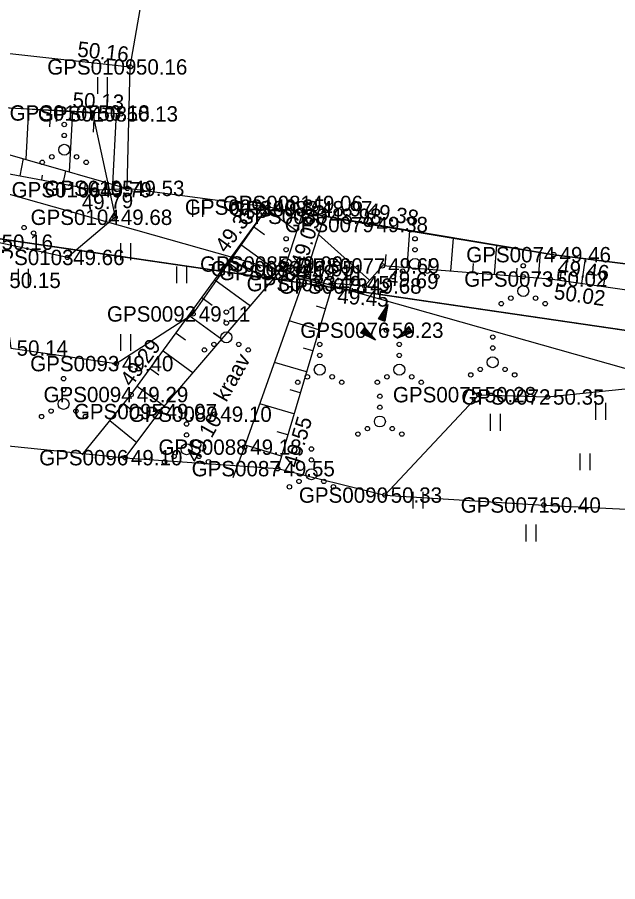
# Model space of a CAD drawing. Extents: x 551623 to 559850, y 6561220 to 6567135.
# Drawn here: x 556014.76 to 556042.11, y 6565327.62 to 6565367.01 of the extents above; entities that cross this region are included whole.
import ezdxf

# ---------------------------------------------------------------- set-up
doc = ezdxf.new("R2010")
doc.units = 0
for name, color, linetype in [('HALJASTUS', 7, 'Continuous'), ('KORGUS-EH2000', 7, 'Continuous'), ('KPOHULIIN', 7, 'Continuous'), ('MOOTKORG-EH2000', 7, 'Continuous'), ('MOOTMPUNKT', 7, 'Continuous'), ('MOOTNR', 7, 'Continuous'), ('MOOTPIIR', 7, 'Continuous'), ('PIIR', 7, 'Continuous'), ('RELJEEF', 7, 'Continuous'), ('TEE', 7, 'Continuous'), ('VEEKOGU', 7, 'Continuous')]:
    doc.layers.add(name, color=color, linetype=linetype)

msp = doc.modelspace()

# ---------------------------------------------------------------- linework, layer by layer
at = {"layer": 'HALJASTUS'}
for p, q in [((556018.404, 6565364.285), (556018.404, 6565363.524)), ((556018.859, 6565364.285), (556018.859, 6565363.524)), ((556022.737, 6565358.682), (556022.737, 6565357.921)), ((556023.192, 6565358.682), (556023.192, 6565357.921)), ((556019.463, 6565356.707), (556019.463, 6565355.946)), ((556019.918, 6565356.707), (556019.918, 6565355.946)), ((556014.792, 6565355.55), (556014.792, 6565354.789)), ((556015.247, 6565355.55), (556015.247, 6565354.789)), ((556022.015, 6565355.647), (556022.015, 6565354.886)), ((556022.47, 6565355.647), (556022.47, 6565354.886)), ((556019.463, 6565352.563), (556019.463, 6565351.802)), ((556019.918, 6565352.563), (556019.918, 6565351.802)), ((556041.092, 6565349.431), (556041.092, 6565348.67)), ((556041.548, 6565349.431), (556041.548, 6565348.67)), ((556036.301, 6565348.931), (556036.301, 6565348.17)), ((556036.756, 6565348.931), (556036.756, 6565348.17)), ((556040.382, 6565347.124), (556040.382, 6565346.363)), ((556040.837, 6565347.124), (556040.837, 6565346.363)), ((556032.777, 6565345.384), (556032.777, 6565344.623)), ((556033.232, 6565345.384), (556033.232, 6565344.623)), ((556037.924, 6565343.888), (556037.924, 6565343.127)), ((556038.38, 6565343.888), (556038.38, 6565343.127))]:
    msp.add_line(p, q, dxfattribs=at)
for points in [[(555993.466, 6565364.067), (556009.179, 6565363.204), (556018.189, 6565362.647), (556019.213, 6565357.893), (556017.04, 6565356.065), (556013.782, 6565356.759), (556014.467, 6565351.934), (556019.265, 6565351.225), (556022.764, 6565353.488), (556026.171, 6565358.357)], [(556031.505, 6565345.235), (556035.788, 6565349.81), (556038.903, 6565349.705), (556046.564, 6565350.502), (556056.627, 6565352.652), (556057.538, 6565354.856)]]:
    msp.add_lwpolyline(points, dxfattribs=at)
for centre, radius in [((556016.896, 6565362.122), 0.1), ((556016.896, 6565361.622), 0.1), ((556016.896, 6565360.972), 0.25), ((556016.331, 6565360.647), 0.1), ((556017.461, 6565360.647), 0.1), ((556015.896, 6565360.397), 0.1), ((556017.896, 6565360.397), 0.1), ((556015.066, 6565357.424), 0.1), ((556015.501, 6565357.174), 0.1), ((556027.003, 6565356.913), 0.1), ((556032.874, 6565356.913), 0.1), ((556027.003, 6565356.413), 0.1), ((556032.874, 6565356.413), 0.1), ((556027.003, 6565355.763), 0.25), ((556032.874, 6565355.763), 0.25), ((556026.438, 6565355.438), 0.1), ((556027.568, 6565355.438), 0.1), ((556032.309, 6565355.438), 0.1), ((556033.439, 6565355.438), 0.1), ((556037.804, 6565355.683), 0.1), ((556026.003, 6565355.188), 0.1), ((556028.003, 6565355.188), 0.1), ((556031.874, 6565355.188), 0.1), ((556033.874, 6565355.188), 0.1), ((556037.804, 6565355.183), 0.1), ((556037.804, 6565354.533), 0.25), ((556037.239, 6565354.208), 0.1), ((556038.369, 6565354.208), 0.1), ((556036.804, 6565353.958), 0.1), ((556038.804, 6565353.958), 0.1), ((556024.279, 6565353.575), 0.1), ((556024.279, 6565353.075), 0.1), ((556024.279, 6565352.425), 0.25), ((556036.413, 6565352.437), 0.1), ((556023.279, 6565351.85), 0.1), ((556023.714, 6565352.1), 0.1), ((556024.844, 6565352.1), 0.1), ((556025.279, 6565351.85), 0.1), ((556028.535, 6565352.099), 0.1), ((556032.158, 6565352.099), 0.1), ((556036.413, 6565351.937), 0.1), ((556028.535, 6565351.599), 0.1), ((556032.158, 6565351.599), 0.1), ((556028.535, 6565350.949), 0.25), ((556032.158, 6565350.949), 0.25), ((556036.413, 6565351.287), 0.25), ((556035.413, 6565350.712), 0.1), ((556035.848, 6565350.962), 0.1), ((556036.978, 6565350.962), 0.1), ((556037.413, 6565350.712), 0.1), ((556016.864, 6565350.539), 0.1), ((556027.535, 6565350.374), 0.1), ((556027.97, 6565350.624), 0.1), ((556029.1, 6565350.624), 0.1), ((556029.535, 6565350.374), 0.1), ((556031.158, 6565350.374), 0.1), ((556031.593, 6565350.624), 0.1), ((556032.723, 6565350.624), 0.1), ((556033.158, 6565350.374), 0.1), ((556016.864, 6565350.039), 0.1), ((556016.864, 6565349.389), 0.25), ((556031.273, 6565349.738), 0.1), ((556031.273, 6565349.238), 0.1), ((556015.864, 6565348.814), 0.1), ((556016.299, 6565349.064), 0.1), ((556017.429, 6565349.064), 0.1), ((556017.864, 6565348.814), 0.1), ((556031.273, 6565348.588), 0.25), ((556022.467, 6565348.474), 0.1), ((556022.467, 6565347.974), 0.1), ((556030.273, 6565348.013), 0.1), ((556030.708, 6565348.263), 0.1), ((556031.838, 6565348.263), 0.1), ((556032.273, 6565348.013), 0.1), ((556022.467, 6565347.324), 0.25), ((556028.155, 6565347.335), 0.1), ((556021.467, 6565346.749), 0.1), ((556021.902, 6565346.999), 0.1), ((556023.032, 6565346.999), 0.1), ((556023.467, 6565346.749), 0.1), ((556028.155, 6565346.835), 0.1), ((556028.155, 6565346.185), 0.25), ((556027.155, 6565345.61), 0.1), ((556027.59, 6565345.86), 0.1), ((556028.72, 6565345.86), 0.1), ((556029.155, 6565345.61), 0.1)]:
    msp.add_circle(centre, radius, dxfattribs=at)
at = {"layer": 'KORGUS-EH2000'}
for centre in [(556019.902, 6565364.745), (556019.475, 6565362.606), (556018.278, 6565359.149), (556026.171, 6565358.357), (556030.86, 6565357.563), (556039.198, 6565356.19), (556017.04, 6565356.065), (556027.486, 6565355.551), (556031.391, 6565355.68), (556039.035, 6565355.08), (556029.124, 6565354.87), (556022.764, 6565353.488), (556031.569, 6565352.746), (556019.943, 6565349.815), (556035.788, 6565349.81), (556038.903, 6565349.705), (556023.747, 6565348.921), (556026.62, 6565346.439), (556031.505, 6565345.235), (556038.736, 6565344.782)]:
    msp.add_circle(centre, 0.1, dxfattribs=at)
at = {"layer": 'KPOHULIIN'}
msp.add_lwpolyline([(555766.29, 6565358.132), (555774.476, 6565357.809), (555774.476, 6565357.809), (555822.758, 6565358.143), (555870.36, 6565358.416), (555918.911, 6565358.624), (555918.911, 6565358.624), (555966.511, 6565359.063), (556012.012, 6565359.614), (556063.102, 6565345.172), (556063.102, 6565345.172), (556112.628, 6565331.115), (556160.567, 6565309.951), (556211.02, 6565287.529)], dxfattribs=at)
at = {"layer": 'MOOTMPUNKT'}
for centre in [(556019.902, 6565364.745), (556018.189, 6565362.647), (556019.475, 6565362.606), (556018.278, 6565359.149), (556019.769, 6565359.212), (556026.171, 6565358.357), (556027.899, 6565358.524), (556028.333, 6565358.284), (556019.213, 6565357.893), (556028.747, 6565357.937), (556030.86, 6565357.563), (556039.198, 6565356.19), (556017.04, 6565356.065), (556027.003, 6565355.763), (556027.486, 6565355.551), (556031.391, 6565355.68), (556027.931, 6565355.378), (556039.035, 6565355.08), (556029.124, 6565354.87), (556030.571, 6565354.761), (556022.764, 6565353.488), (556031.569, 6565352.746), (556019.265, 6565351.225), (556019.943, 6565349.815), (556035.788, 6565349.81), (556038.903, 6565349.705), (556021.253, 6565349.04), (556023.747, 6565348.921), (556025.108, 6565347.419), (556019.674, 6565346.939), (556026.62, 6565346.439), (556031.505, 6565345.235), (556038.736, 6565344.782)]:
    msp.add_circle(centre, 0.1, dxfattribs=at)
at = {"layer": 'MOOTPIIR'}
for points in [[(556057.929, 6565353.821), (556039.198, 6565356.19), (556028.747, 6565357.937), (556026.171, 6565358.357), (556019.769, 6565359.212), (556019.902, 6565364.745), (556021.558, 6565374.265), (556015.152, 6565374.331), (556012.73, 6565375.394), (555993.907, 6565375.821), (555986.511, 6565374.867), (555981.259, 6565364.203), (555966.865, 6565362.926), (555942.733, 6565362.646), (555918.997, 6565362.459), (555899.983, 6565361.794), (555880.558, 6565361.528), (555870.644, 6565361.764), (555852.219, 6565361.421)], [(555839.435, 6565355.215), (555871.496, 6565354.829), (555900.084, 6565356.085), (555918.855, 6565355.549), (555942.97, 6565356.268), (555966.756, 6565353.298), (555985.371, 6565350.605), (555996.731, 6565349.216), (556009.016, 6565348.025), (556019.674, 6565346.939), (556026.62, 6565346.439), (556031.505, 6565345.235), (556038.736, 6565344.782), (556063.163, 6565343.594)]]:
    msp.add_lwpolyline(points, dxfattribs=at)
at = {"layer": 'PIIR'}
for points in [[(555860.69, 6565787.05), (556134.83, 6565867.67), (556136.76, 6565868.24), (556138.68, 6565868.81), (556304.72, 6565917.64), (556407.28, 6565947.65), (556409.2, 6565948.21), (556411.12, 6565948.77), (556555.39, 6565990.98), (556602.55, 6565855.41), (556340.11, 6565662.55), (556145.23, 6565518.55), (556122.95, 6565328.71), (556065.95, 6565349.3), (555986.85, 6565360.88), (555889.86, 6565359.34), (555877.35, 6565546.73)], [(555766.77, 6565362.31), (555785.15, 6565359.9), (555792.17, 6565359.86), (555889.86, 6565359.34), (555986.85, 6565360.88), (556065.95, 6565349.3), (556122.95, 6565328.71), (556199.38, 6565295.85), (556198.85, 6565282.81), (556195.83, 6565275.41), (556189.32, 6565262.35), (556176.88, 6565235.57), (556133.25, 6565139.15), (556097.67, 6565060.64), (555982.17, 6564796.57), (555965.54, 6564731.83), (555935.2, 6564801.96), (555871.92, 6565015.39), (555870.22, 6565021.13), (555867.36, 6565030.76)]]:
    msp.add_lwpolyline(points, close=True, dxfattribs=at)
at = {"layer": 'RELJEEF'}
for p, q in [((556015.267, 6565362.821), (556015.15, 6565360.535)), ((556016.266, 6565362.77), (556016.227, 6565362.015)), ((556017.265, 6565362.719), (556017.124, 6565359.97)), ((556018.263, 6565362.668), (556018.218, 6565361.774)), ((556019.262, 6565362.617), (556019.098, 6565359.404)), ((556014.887, 6565359.781), (556015.034, 6565360.568)), ((556016.853, 6565359.415), (556016.965, 6565360.015)), ((556015.87, 6565359.598), (556015.909, 6565359.806)), ((556018.828, 6565359.172), (556018.815, 6565359.485)), ((556017.836, 6565359.232), (556017.865, 6565359.384)), ((556026.112, 6565358.276), (556027.492, 6565357.27)), ((556025.523, 6565357.468), (556026.016, 6565357.108)), ((556030.807, 6565355.025), (556028.481, 6565357.102)), ((556032.51, 6565355.592), (556032.642, 6565357.27)), ((556034.504, 6565355.436), (556034.622, 6565356.944)), ((556024.933, 6565356.66), (556026.681, 6565355.386)), ((556036.498, 6565355.279), (556036.603, 6565356.618)), ((556038.492, 6565355.123), (556038.583, 6565356.292)), ((556031.513, 6565355.67), (556031.555, 6565356.199)), ((556033.507, 6565355.514), (556033.545, 6565355.992)), ((556040.475, 6565354.873), (556040.639, 6565356.008)), ((556024.344, 6565355.852), (556024.85, 6565355.483)), ((556029.927, 6565354.81), (556029.992, 6565355.674)), ((556035.501, 6565355.357), (556035.534, 6565355.784)), ((556037.495, 6565355.201), (556037.524, 6565355.577)), ((556039.485, 6565355.015), (556039.534, 6565355.351)), ((556023.755, 6565355.044), (556025.377, 6565353.861)), ((556029.069, 6565354.683), (556027.817, 6565355.055)), ((556041.465, 6565354.73), (556041.515, 6565355.076)), ((556023.166, 6565354.236), (556023.634, 6565353.895)), ((556031.214, 6565353.272), (556031.634, 6565353.912)), ((556031.634, 6565353.912), (556031.494, 6565353.157)), ((556028.784, 6565353.725), (556028.393, 6565353.841)), ((556031.314, 6565353.422), (556031.564, 6565353.527)), ((556031.364, 6565353.497), (556031.489, 6565353.552)), ((556031.414, 6565353.572), (556031.584, 6565353.647)), ((556031.464, 6565353.647), (556031.594, 6565353.707)), ((556031.489, 6565353.552), (556031.574, 6565353.587)), ((556031.509, 6565353.722), (556031.609, 6565353.762)), ((556031.559, 6565353.797), (556031.619, 6565353.822)), ((556031.609, 6565353.872), (556031.629, 6565353.882)), ((556022.577, 6565353.428), (556024.073, 6565352.337)), ((556028.499, 6565352.766), (556027.147, 6565353.168)), ((556031.214, 6565353.272), (556031.539, 6565353.412)), ((556031.214, 6565353.272), (556031.494, 6565353.157)), ((556031.214, 6565353.272), (556031.214, 6565353.272)), ((556031.264, 6565353.347), (556031.549, 6565353.467)), ((556031.279, 6565353.247), (556031.529, 6565353.352)), ((556031.344, 6565353.217), (556031.519, 6565353.292)), ((556031.414, 6565353.192), (556031.509, 6565353.232)), ((556031.479, 6565353.167), (556031.494, 6565353.172)), ((556030.573, 6565352.871), (556030.388, 6565352.631)), ((556030.488, 6565352.761), (556030.513, 6565352.576)), ((556030.528, 6565352.816), (556030.563, 6565352.546)), ((556030.573, 6565352.871), (556031.078, 6565352.301)), ((556030.573, 6565352.871), (556030.618, 6565352.521)), ((556030.573, 6565352.871), (556030.573, 6565352.871)), ((556030.633, 6565352.806), (556030.673, 6565352.496)), ((556030.693, 6565352.736), (556030.728, 6565352.471)), ((556032.052, 6565352.366), (556032.592, 6565352.911)), ((556032.762, 6565352.661), (556032.412, 6565352.726)), ((556032.722, 6565352.716), (556032.457, 6565352.771)), ((556032.682, 6565352.776), (556032.497, 6565352.811)), ((556032.642, 6565352.836), (556032.542, 6565352.856)), ((556032.602, 6565352.896), (556032.582, 6565352.896)), ((556032.762, 6565352.661), (556032.592, 6565352.911)), ((556021.988, 6565352.62), (556022.418, 6565352.306)), ((556031.078, 6565352.301), (556030.388, 6565352.631)), ((556030.398, 6565352.646), (556030.403, 6565352.626)), ((556030.443, 6565352.701), (556030.458, 6565352.601)), ((556030.753, 6565352.671), (556030.768, 6565352.531)), ((556030.768, 6565352.531), (556030.783, 6565352.441)), ((556030.808, 6565352.601), (556030.838, 6565352.416)), ((556030.868, 6565352.536), (556030.888, 6565352.391)), ((556030.928, 6565352.466), (556030.943, 6565352.366)), ((556030.988, 6565352.401), (556030.998, 6565352.336)), ((556031.048, 6565352.331), (556031.053, 6565352.311)), ((556032.762, 6565352.661), (556032.052, 6565352.366)), ((556032.092, 6565352.381), (556032.077, 6565352.386)), ((556032.177, 6565352.416), (556032.117, 6565352.431)), ((556032.262, 6565352.451), (556032.157, 6565352.471)), ((556032.342, 6565352.486), (556032.202, 6565352.516)), ((556032.427, 6565352.521), (556032.242, 6565352.556)), ((556032.377, 6565352.581), (556032.287, 6565352.601)), ((556032.592, 6565352.591), (556032.327, 6565352.641)), ((556032.677, 6565352.626), (556032.372, 6565352.686)), ((556032.512, 6565352.556), (556032.377, 6565352.581)), ((556032.762, 6565352.661), (556032.762, 6565352.661)), ((556021.398, 6565351.812), (556022.769, 6565350.812)), ((556028.214, 6565351.807), (556027.794, 6565351.932)), ((556027.93, 6565350.849), (556026.477, 6565351.28)), ((556020.809, 6565351.004), (556021.202, 6565350.718)), ((556020.22, 6565350.196), (556021.465, 6565349.288)), ((556027.645, 6565349.89), (556027.194, 6565350.024)), ((556019.609, 6565349.405), (556019.966, 6565349.115)), ((556027.36, 6565348.932), (556025.808, 6565349.393)), ((556018.979, 6565348.628), (556020.199, 6565347.637)), ((556027.076, 6565347.973), (556026.595, 6565348.116)), ((556026.791, 6565347.014), (556025.138, 6565347.505))]:
    msp.add_line(p, q, dxfattribs=at)
for points in [[(555993.3, 6565364.022), (556010.432, 6565361.886), (556019.769, 6565359.212)], [(556019.475, 6565362.606), (556010.471, 6565363.067), (555993.3, 6565364.022), (556010.587, 6565360.582), (556018.278, 6565359.149), (556019.769, 6565359.212)], [(556017.718, 6565347.076), (556019.943, 6565349.815), (556026.171, 6565358.357)], [(556028.747, 6565357.937), (556030.86, 6565357.563), (556039.198, 6565356.19), (556057.929, 6565353.821), (556064.592, 6565351.829), (556088.936, 6565343.79), (556116.503, 6565332.956), (556130.776, 6565326.047), (556146.22, 6565319.093), (556161.9, 6565312.316), (556182.877, 6565303.186), (556190.092, 6565300.488), (556198.955, 6565296.142)], [(556198.951, 6565295.377), (556198.427, 6565295.218), (556190.116, 6565299.053), (556182.032, 6565302.053), (556161.506, 6565310.813), (556145.447, 6565317.76), (556130.182, 6565324.921), (556115.272, 6565331.25), (556088.426, 6565342.556), (556064.014, 6565350.434), (556058.394, 6565352.289), (556039.035, 6565355.08), (556031.391, 6565355.68), (556030.571, 6565354.761), (556029.124, 6565354.87), (556026.62, 6565346.439)]]:
    msp.add_lwpolyline(points, dxfattribs=at)
at = {"layer": 'TEE'}
msp.add_lwpolyline([(555982.622, 6565367.458), (555985.438, 6565367.33), (555992.704, 6565367.102), (556008.109, 6565366.058), (556019.902, 6565364.745)], dxfattribs=at)
at = {"layer": 'VEEKOGU'}
for points in [[(556019.674, 6565346.939), (556021.253, 6565349.04), (556027.003, 6565355.763), (556027.899, 6565358.524)], [(556024.584, 6565346.037), (556025.108, 6565347.419), (556027.931, 6565355.378), (556028.747, 6565357.937)]]:
    msp.add_lwpolyline(points, dxfattribs=at)

# ---------------------------------------------------------------- texts
at = {"layer": 'KORGUS-EH2000'}
for s, rotation, p in [(' 50.16', 353.6483, (556017.208, 6565365.248)), (' 50.13', 357.0729, (556017.004, 6565362.908)), (' 49.79', 2.4082, (556017.45, 6565358.215)), (' 49.35', 53.9006, (556024.121, 6565356.013)), (' 49.38', 350.6532, (556030.403, 6565357.927)), (' 49.05', 72.7816, (556027.794, 6565355.326)), (' 49.46', 352.7917, (556039.088, 6565355.322)), (' 49.69', 355.5142, (556031.323, 6565354.808)), (' 50.02', 351.7963, (556038.91, 6565354.214)), (' 49.45', 355.6955, (556029.058, 6565353.998)), (' 49.29', 53.9006, (556019.801, 6565349.919)), (' 49.10', 60.5805, (556022.839, 6565346.432)), (' 49.55', 73.4589, (556027.459, 6565346.189))]:
    msp.add_text(s, height=0.7, rotation=rotation, dxfattribs=at).set_placement(p)
for s, p in [(' 49.66', (556017.04, 6565355.715)), (' 49.11', (556022.764, 6565353.138)), (' 50.23', (556031.569, 6565352.396)), (' 50.14', (556014.467, 6565351.584)), (' 50.28', (556035.788, 6565349.46)), (' 50.35', (556038.903, 6565349.355)), (' 50.33', (556031.505, 6565344.885)), (' 50.40', (556038.736, 6565344.432))]:
    msp.add_text(s, height=0.7, dxfattribs=at).set_placement(p)
at = {"layer": 'MOOTKORG-EH2000'}
for s, p in [(' 50.16', (556019.902, 6565364.395)), (' 50.18', (556018.189, 6565362.297)), (' 50.13', (556019.475, 6565362.256)), (' 49.79', (556018.278, 6565358.799)), (' 49.53', (556019.769, 6565358.862)), (' 49.35', (556026.171, 6565358.008)), (' 49.06', (556027.899, 6565358.174)), (' 48.97', (556028.333, 6565357.934)), (' 49.68', (556019.213, 6565357.543)), (' 48.98', (556028.747, 6565357.587)), (' 49.38', (556030.86, 6565357.213)), (' 50.16', (556013.782, 6565356.409)), (' 49.66', (556017.04, 6565355.715)), (' 49.46', (556039.198, 6565355.84)), (' 49.09', (556027.003, 6565355.413)), (' 49.05', (556027.486, 6565355.201)), (' 49.69', (556031.391, 6565355.33)), (' 49.11', (556027.931, 6565355.028)), (' 50.15', (556014.135, 6565354.669)), (' 49.45', (556029.124, 6565354.52)), (' 49.68', (556030.571, 6565354.411)), (' 50.02', (556039.035, 6565354.73)), (' 49.11', (556022.764, 6565353.138)), (' 50.23', (556031.569, 6565352.396)), (' 50.14', (556014.467, 6565351.584)), (' 49.40', (556019.265, 6565350.875)), (' 49.29', (556019.943, 6565349.465)), (' 50.28', (556035.788, 6565349.46)), (' 50.35', (556038.903, 6565349.355)), (' 49.07', (556021.253, 6565348.69)), (' 49.10', (556023.747, 6565348.571)), (' 49.18', (556025.108, 6565347.069)), (' 49.10', (556019.674, 6565346.589)), (' 49.55', (556026.62, 6565346.089)), (' 50.33', (556031.505, 6565344.885)), (' 50.40', (556038.736, 6565344.432))]:
    msp.add_text(s, height=0.7, dxfattribs=at).set_placement(p)
at = {"layer": 'MOOTNR'}
for s, p in [('GPS0109 ', (556016.123, 6565364.395)), ('GPS0107 ', (556014.409, 6565362.297)), ('GPS0108 ', (556015.695, 6565362.256)), ('GPS0106 ', (556014.499, 6565358.799)), ('GPS0105 ', (556015.989, 6565358.862)), ('GPS0091 ', (556022.392, 6565358.008)), ('GPS0081 ', (556024.119, 6565358.174)), ('GPS0082 ', (556024.414, 6565357.934)), ('GPS0104 ', (556015.364, 6565357.543)), ('GPS0080 ', (556024.828, 6565357.587)), ('GPS0079 ', (556026.941, 6565357.213)), ('GPS0103 ', (556013.26, 6565355.715)), ('GPS0074 ', (556035.208, 6565355.84)), ('GPS0085 ', (556023.083, 6565355.413)), ('GPS0086 ', (556023.567, 6565355.201)), ('GPS0077 ', (556027.471, 6565355.33)), ('GPS0084 ', (556023.942, 6565355.028)), ('GPS0083 ', (556025.204, 6565354.52)), ('GPS0078 ', (556026.651, 6565354.411)), ('GPS0073 ', (556035.115, 6565354.73)), ('GPS0092 ', (556018.844, 6565353.138)), ('GPS0076 ', (556027.649, 6565352.396)), ('GPS0093 ', (556015.345, 6565350.875)), ('GPS0094 ', (556015.953, 6565349.465)), ('GPS0075 ', (556031.868, 6565349.46)), ('GPS0072 ', (556034.983, 6565349.355)), ('GPS0095 ', (556017.334, 6565348.69)), ('GPS0089 ', (556019.828, 6565348.571)), ('GPS0088 ', (556021.188, 6565347.069)), ('GPS0096 ', (556015.754, 6565346.589)), ('GPS0087 ', (556022.7, 6565346.089)), ('GPS0090 ', (556027.585, 6565344.885)), ('GPS0071 ', (556034.956, 6565344.432))]:
    msp.add_text(s, height=0.7, dxfattribs=at).set_placement(p)
at = {"layer": 'VEEKOGU'}
msp.add_text('kraav', height=0.7, rotation=60.5349, dxfattribs=at).set_placement((556024.278, 6565349.438))

doc.saveas('drawing.dxf')
